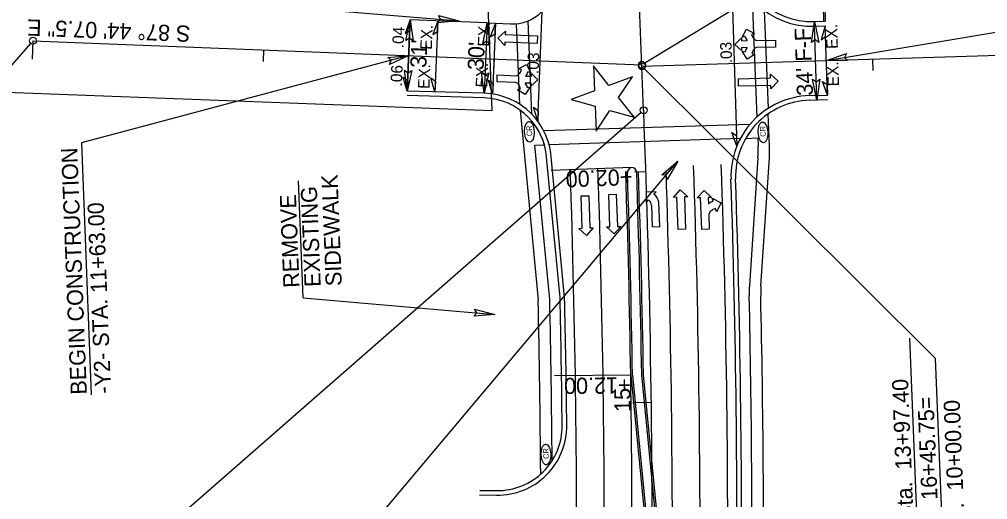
# Model space of a CAD drawing. Extents: x 1627861 to 1629601, y 761281 to 766239.
# Drawn here: x 1628215.6 to 1628635.3, y 761933.4 to 762141.5 of the extents above; entities that cross this region are included whole.
import ezdxf

# ---------------------------------------------------------------- set-up
doc = ezdxf.new("R2010")
doc.units = 0
for name, color, linetype in [('Cogo Default Point CELL', 7, 'Continuous'), ('Default', 7, 'Continuous'), ('Exist Other Culture Sign Leader', 7, 'Continuous'), ('Exist Property Tie Line Leader', 7, 'Continuous'), ('Exist Property Tie Line Text', 7, 'Continuous'), ('Exist Right of Way Line Leader', 7, 'Continuous'), ('Exist Right of Way Monument Leader', 7, 'Continuous'), ('Exist Right of Way Monument Text', 7, 'Continuous'), ('Exist Utilities Gas Meter CELL', 7, 'Continuous'), ('Exist Utilities Gas Meter Cogo Elevation', 7, 'Continuous'), ('Exist Utilities Gas Meter Cogo Number', 7, 'Continuous'), ('Exist Utilities Gas UG Line', 7, 'Continuous'), ('Exist Utilities Other Unknown UG SUE Text', 7, 'Continuous'), ('Exist Utilities Power UG Cable SUE LOS B Cogo Elevation', 7, 'Continuous'), ('Exist Utilities Power UG Cable SUE LOS B Cogo Point CELL', 7, 'Continuous'), ('Exist Utilities Telephone UG Cable SUE LOS B Cogo Comment', 7, 'Continuous'), ('Exist Utilities Telephone UG Cable SUE LOS B Cogo Number', 7, 'Continuous'), ('Exist Utilities Water Fire Hydrant Cogo Elevation', 7, 'Continuous'), ('Exist Utilities Water Fire Hydrant Cogo Number', 7, 'Continuous'), ('Exist Utilities Water Meter Cogo Elevation', 7, 'Continuous'), ('Exist Utilities Water UG Line SUE LOS B Cogo Number', 7, 'Continuous'), ('Exist Utilities Water Valve CELL', 7, 'Continuous'), ('Scratch_Level_0', 7, 'Continuous'), ('Typical Terminator CELL', 7, 'Continuous')]:
    doc.layers.add(name, color=color, linetype=linetype)

msp = doc.modelspace()

# ---------------------------------------------------------------- linework, layer by layer
at = {"layer": 'Default'}
msp.add_line((1628484.93, 762039.42), (1628484.96, 762039.39), dxfattribs=at)
at = {"layer": 'Exist Other Culture Sign Leader'}
msp.add_line((1628565.43, 762123.69), (1628664.46, 762140.15), dxfattribs=at)
at = {"layer": 'Exist Property Tie Line Text'}
for p, q in [((1628321.43, 762128.28), (1628321.23, 762123.29)), ((1628421.35, 762124.33), (1628421.15, 762119.34)), ((1628585.42, 762124.31), (1628585.58, 762119.32)), ((1628487.2, 762075.46), (1628482.2, 762075.29))]:
    msp.add_line(p, q, dxfattribs=at)
at = {"layer": 'Exist Right of Way Line Leader'}
for p, q in [((1628486.68, 762122.66), (1628711.64, 762259.34)), ((1628220.51, 762131.12), (1628175.92, 762080.71)), ((1628486.53, 762120.12), (1628612.77, 761994.56)), ((1628485.09, 762101.12), (1628288.18, 761928.9)), ((1628606.22, 761887.58), (1628601.66, 762003.32)), ((1628617.3, 761879.65), (1628612.77, 761994.56))]:
    msp.add_line(p, q, dxfattribs=at)
for centre in [(1628221.51, 762132.23), (1628485.45, 762121.8), (1628485.47, 762121.18), (1628485.47, 762121.18), (1628486.22, 762102.11)]:
    msp.add_circle(centre, 1.5, dxfattribs=at)
at = {"layer": 'Exist Right of Way Monument Leader'}
for p, q in [((1628423.01, 762133.37), (1628426.3, 762136.43)), ((1628426.3, 762136.43), (1628426.23, 762134.94)), ((1628528.86, 762133.77), (1628530.79, 762137.31)), ((1628530.79, 762137.31), (1628534.24, 762135.38)), ((1628426.03, 762130.14), (1628423.01, 762133.37)), ((1628426.09, 762131.64), (1628426.03, 762130.14)), ((1628440.08, 762131.04), (1628426.09, 762131.64)), ((1628426.23, 762134.94), (1628440.22, 762134.34)), ((1628440.22, 762134.34), (1628440.08, 762131.04)), ((1628525.75, 762130.63), (1628528.57, 762133.52)), ((1628528.57, 762133.52), (1628528.6, 762132.25)), ((1628528.6, 762132.25), (1628531.13, 762132.3)), ((1628530.12, 762134.18), (1628528.86, 762133.77)), ((1628534.24, 762135.38), (1628532.98, 762134.97)), ((1628535.13, 762132.37), (1628543.37, 762132.53)), ((1628543.37, 762132.53), (1628543.42, 762129.51)), ((1628528.68, 762127.96), (1628525.75, 762130.63)), ((1628531.14, 762129.27), (1628528.65, 762129.23)), ((1628528.65, 762129.23), (1628528.68, 762127.96)), ((1628531.04, 762124.3), (1628528.98, 762127.72)), ((1628528.98, 762127.72), (1628530.25, 762127.36)), ((1628543.42, 762129.51), (1628535.14, 762129.35)), ((1628534.41, 762126.31), (1628531.04, 762124.3)), ((1628533.14, 762126.68), (1628534.41, 762126.31)), ((1628431.97, 762120.07), (1628435.46, 762121.88)), ((1628433.22, 762119.63), (1628431.97, 762120.07)), ((1628435.46, 762121.88), (1628437.31, 762118.33)), ((1628422.65, 762114.42), (1628422.78, 762117.44)), ((1628422.78, 762117.44), (1628431.06, 762117.08)), ((1628435.05, 762116.92), (1628437.54, 762116.81)), ((1628437.31, 762118.33), (1628436.06, 762118.78)), ((1628440.35, 762115.23), (1628437.36, 762112.52)), ((1628437.54, 762116.81), (1628437.59, 762118.08)), ((1628437.59, 762118.08), (1628440.35, 762115.23)), ((1628527.27, 762115.79), (1628541.27, 762116.19)), ((1628527.37, 762112.49), (1628527.27, 762115.79)), ((1628541.27, 762116.19), (1628541.22, 762117.69)), ((1628541.22, 762117.69), (1628544.46, 762114.68)), ((1628430.88, 762114.07), (1628422.65, 762114.42)), ((1628431.58, 762111.01), (1628432.87, 762111.35)), ((1628434.91, 762108.87), (1628431.58, 762111.01)), ((1628437.41, 762113.79), (1628434.88, 762113.9)), ((1628437.05, 762112.29), (1628434.91, 762108.87)), ((1628435.77, 762111.96), (1628437.05, 762112.29)), ((1628437.36, 762112.52), (1628437.41, 762113.79)), ((1628541.36, 762112.89), (1628527.37, 762112.49)), ((1628541.4, 762111.39), (1628541.36, 762112.89)), ((1628544.46, 762114.68), (1628541.4, 762111.39)), ((1628459.1, 762064.96), (1628462.39, 762065.08)), ((1628459.6, 762050.97), (1628459.1, 762064.96)), ((1628462.39, 762065.08), (1628462.9, 762051.09)), ((1628471.07, 762065.62), (1628474.37, 762065.74)), ((1628471.57, 762051.63), (1628471.07, 762065.62)), ((1628474.37, 762065.74), (1628474.87, 762051.75)), ((1628491.63, 762066.77), (1628487.24, 762066.66)), ((1628487.24, 762066.66), (1628487.35, 762062.16)), ((1628490.62, 762065.68), (1628491.63, 762066.77)), ((1628499.12, 762064.37), (1628502.11, 762067.63)), ((1628502.11, 762067.63), (1628505.42, 762064.6)), ((1628505.42, 762064.6), (1628503.92, 762064.54)), ((1628503.92, 762064.54), (1628504.42, 762050.55)), ((1628509.38, 762064.15), (1628512.42, 762067.36)), ((1628512.42, 762067.36), (1628515.68, 762064.37)), ((1628487.35, 762062.16), (1628488.36, 762063.25)), ((1628489.6, 762060.79), (1628489.93, 762051.65)), ((1628493.22, 762051.77), (1628492.85, 762062.31)), ((1628500.62, 762064.43), (1628499.12, 762064.37)), ((1628501.12, 762050.44), (1628500.62, 762064.43)), ((1628510.88, 762064.2), (1628509.38, 762064.15)), ((1628511.38, 762050.41), (1628510.88, 762064.2)), ((1628515.68, 762064.37), (1628514.18, 762064.32)), ((1628514.18, 762064.32), (1628514.28, 762061.47)), ((1628516.34, 762062.65), (1628515.89, 762064.08)), ((1628515.89, 762064.08), (1628519.82, 762062.02)), ((1628519.82, 762062.02), (1628517.76, 762058.09)), ((1628514.44, 762056.98), (1628514.67, 762050.53)), ((1628517.76, 762058.09), (1628517.31, 762059.48)), ((1628458.1, 762050.91), (1628459.6, 762050.97)), ((1628461.41, 762047.88), (1628458.1, 762050.91)), ((1628464.4, 762051.14), (1628461.41, 762047.88)), ((1628462.9, 762051.09), (1628464.4, 762051.14)), ((1628470.08, 762051.57), (1628471.57, 762051.63)), ((1628473.39, 762048.54), (1628470.08, 762051.57)), ((1628476.37, 762051.8), (1628473.39, 762048.54)), ((1628474.87, 762051.75), (1628476.37, 762051.8)), ((1628489.93, 762051.65), (1628493.22, 762051.77)), ((1628504.42, 762050.55), (1628501.12, 762050.44)), ((1628514.67, 762050.53), (1628511.38, 762050.41))]:
    msp.add_line(p, q, dxfattribs=at)
for centre, radius, start, end in [((1628534.02, 762135.03), 4, 192.3559, 223.2455), ((1628536.88, 762135.86), 4, 192.725, 223.6552), ((1628535.73, 762134.57), 2.28, 220.1651, 254.9311), ((1628534.18, 762126.67), 4, 139.3352, 170.1117), ((1628537.07, 762125.95), 4, 138.5287, 169.7414), ((1628535.87, 762127.2), 2.28, 109.0209, 142.0188), ((1628429.34, 762120.59), 4, 315.0139, 346.2266), ((1628430.46, 762119.28), 2.28, 285.5061, 318.504), ((1628432.18, 762119.7), 4, 315.8204, 346.5968), ((1628430.15, 762111.91), 2.28, 36.6503, 71.4163), ((1628428.92, 762110.69), 4, 9.2102, 40.1404), ((1628431.82, 762111.34), 4, 8.841, 39.7307), ((1628487.7, 762061.33), 5.25, 10.7347, 56.0464), ((1628486.34, 762060.69), 3.28, 2.0586, 51.7168), ((1628517.39, 762058.33), 4.43, 103.6494, 134.528), ((1628516.91, 762056.42), 2.52, 131.1317, 167.4437), ((1628518.36, 762055.17), 4.43, 103.7683, 134.6218)]:
    msp.add_arc(centre, radius, start, end, dxfattribs=at)
at = {"layer": 'Exist Right of Way Monument Text'}
for p, q in [((1628418.35, 762139.93), (1628384.99, 762141.3)), ((1628418.35, 762139.92), (1628428.54, 762139.52)), ((1628560.31, 762138.53), (1628564.96, 762138.68)), ((1628417.14, 762109.45), (1628383.77, 762110.42)), ((1628557.96, 762108.45), (1628565.9, 762108.7)), ((1628451.97, 762021.15), (1628446.25, 762080.52)), ((1628415.12, 761935.4), (1628422.5, 761935.31))]:
    msp.add_line(p, q, dxfattribs=at)
for centre, radius, start, end in [((1628559.22, 762173.52), 35, 182.2582, 271.7963), ((1628429.25, 762157.5), 18, 267.7354, 2.2582), ((1628416.27, 762079.46), 30, 2.0159, 88.3359), ((1628559.06, 762073.46), 35, 91.7963, 181.8855), ((1623719.93, 761914.16), 4806.75, 359.5044, 1.88553), ((1623719.93, 761914.16), 4733.25, 0.62309, 1.29528), ((1628422.9, 761965.3), 30, 269.2458, 0.6231)]:
    msp.add_arc(centre, radius, start, end, dxfattribs=at)
at = {"layer": 'Exist Utilities Gas Meter CELL'}
for p, q in [((1628486.22, 762102.11), (1628373.12, 764970.45)), ((1628221.51, 762132.23), (1628485.45, 762121.8)), ((1628221.51, 762132.23), (1628485.45, 762121.8)), ((1628485.47, 762121.18), (1628785.32, 762130.58))]:
    msp.add_line(p, q, dxfattribs=at)
msp.add_arc((1623719.93, 761914.16), 4770, 359.5044, 2.25819, dxfattribs=at)
at = {"layer": 'Exist Utilities Gas Meter Cogo Elevation'}
for p, q in [((1628560.25, 762140.53), (1628564.9, 762140.68)), ((1628417.08, 762107.46), (1628383.71, 762108.53)), ((1628558.02, 762106.45), (1628565.96, 762106.7)), ((1628449.98, 762020.96), (1628444.26, 762080.33)), ((1628415.14, 761937.4), (1628421.53, 761937.32)), ((1628415.14, 761937.4), (1628422.53, 761937.31))]:
    msp.add_line(p, q, dxfattribs=at)
for centre, radius, start, end in [((1628559.22, 762173.52), 33, 182.2582, 271.7963), ((1628416.27, 762079.46), 28, 2.0159, 88.3359), ((1628559.06, 762073.46), 33, 91.7963, 181.8855), ((1623719.93, 761914.16), 4808.75, 359.5044, 1.88551), ((1623719.93, 761914.16), 4731.25, 0.62309, 1.29528), ((1628422.9, 761965.3), 28, 269.2458, 0.6231)]:
    msp.add_arc(centre, radius, start, end, dxfattribs=at)
at = {"layer": 'Exist Utilities Gas Meter Cogo Number'}
for points in [[(1628383.09, 762132.37), (1628384.99, 762141.3), (1628386.24, 762132.2), (1628384.68, 762133.41)], [(1628397.22, 762143.18), (1628406.06, 762140.89), (1628396.91, 762140.04), (1628398.19, 762141.54)], [(1628558.98, 762131.49), (1628560.25, 762140.53), (1628562.13, 762131.54), (1628560.5, 762132.64)], [(1628416.44, 762130.96), (1628418.34, 762139.89), (1628419.59, 762130.78), (1628418.03, 762132)], [(1628375.29, 762124.97), (1628384.38, 762125.79), (1628376.05, 762121.92), (1628376.75, 762123.76)], [(1628574.56, 762123.63), (1628565.43, 762123.69), (1628574.1, 762126.75), (1628573.22, 762124.98)], [(1628385.68, 762119.35), (1628383.77, 762110.42), (1628382.53, 762119.53), (1628384.09, 762118.31)], [(1628419.04, 762118.38), (1628417.14, 762109.45), (1628415.9, 762118.56), (1628417.45, 762117.35)], [(1628562.58, 762115.59), (1628561.32, 762106.55), (1628559.43, 762115.55), (1628561.07, 762114.45)], [(1628494.06, 762074.17), (1628501.04, 762080.06), (1628496.44, 762072.1), (1628495.95, 762074.01)], [(1628412.95, 762015.96), (1628421.78, 762013.63), (1628412.63, 762012.82), (1628413.91, 762014.32)]]:
    msp.add_lwpolyline(points, close=True, dxfattribs=at)
at = {"layer": 'Exist Utilities Gas UG Line'}
for p, q in [((1628480.61, 761987.35), (1628492.92, 761862.47)), ((1628498.42, 761862.44), (1628486.11, 761987.44))]:
    msp.add_line(p, q, dxfattribs=at)
for radius, start, end in [(4790.75, 359.5044, 1.96193), (4802.75, 359.5044, 1.96193), (4737.25, 359.5044, 1.96193), (4749.25, 359.5044, 1.96193), (4761.25, 0.88088, 1.93787), (4766.75, 0.88088, 1.94119), (4778.75, 359.5044, 1.93871), (4761.25, 359.5044, 0.88088)]:
    msp.add_arc((1623719.93, 761914.16), radius, start, end, dxfattribs=at)
at = {"layer": 'Exist Utilities Other Unknown UG SUE Text'}
for p, q in [((1628481.36, 761987.37), (1628493.67, 761862.47)), ((1628497.67, 761862.44), (1628485.36, 761987.43))]:
    msp.add_line(p, q, dxfattribs=at)
for centre, radius, start, end in [((1628481.2, 762075.26), 2, 1.9379, 181.9379), ((1623719.93, 761914.16), 4762, 0.88088, 1.93788), ((1623719.93, 761914.16), 4766, 0.88088, 1.93788)]:
    msp.add_arc(centre, radius, start, end, dxfattribs=at)
at = {"layer": 'Exist Utilities Power UG Cable SUE LOS B Cogo Elevation'}
msp.add_lwpolyline([(1628465.18, 762103.83), (1628465.61, 762093.02), (1628471.61, 762102.01), (1628482.04, 762099.08), (1628475.33, 762107.59), (1628481.34, 762116.59), (1628471.19, 762112.84), (1628464.48, 762121.34), (1628464.91, 762110.52), (1628454.75, 762106.76), (1628465.18, 762103.83)], dxfattribs=at)
at = {"layer": 'Exist Utilities Power UG Cable SUE LOS B Cogo Point CELL'}
msp.add_line((1628561.32, 762106.55), (1628560.31, 762138.53), dxfattribs=at)
at = {"layer": 'Exist Utilities Telephone UG Cable SUE LOS B Cogo Comment'}
for p, q in [((1628533.3, 762150), (1628535.3, 762099.17)), ((1628538.49, 762145.32), (1628540.16, 762102.92)), ((1628437.7, 762100.45), (1628436.11, 762140.86)), ((1628432.53, 762104.67), (1628431.16, 762139.6)), ((1628532.26, 762095.98), (1628442.98, 762093.12)), ((1628528.13, 762089.85), (1628445.26, 762087.19))]:
    msp.add_line(p, q, dxfattribs=at)
at = {"layer": 'Exist Utilities Telephone UG Cable SUE LOS B Cogo Number'}
for p, q in [((1628564.03, 762147.19), (1628564.23, 762140.66)), ((1628564.69, 762147.22), (1628564.9, 762140.68))]:
    msp.add_line(p, q, dxfattribs=at)
at = {"layer": 'Exist Utilities Water Fire Hydrant Cogo Elevation'}
for centre in [(1628436.67, 762092.76), (1628537.95, 762092.52), (1628443.87, 761952.93)]:
    msp.add_ellipse(centre, major_axis=(-0.18, 4.48), ratio=0.462467, dxfattribs=at)
at = {"layer": 'Exist Utilities Water Fire Hydrant Cogo Number'}
for p, q in [((1628420.61, 762102.01), (1628396.89, 762704.96)), ((1628075.65, 762115.08), (1628420.61, 762102.01))]:
    msp.add_line(p, q, dxfattribs=at)
at = {"layer": 'Exist Utilities Water Meter Cogo Elevation'}
for p, q in [((1628221.51, 762132.23), (1628221.19, 762124.24)), ((1628489.53, 761975.49), (1628481.53, 761975.39))]:
    msp.add_line(p, q, dxfattribs=at)
at = {"layer": 'Exist Utilities Water UG Line SUE LOS B Cogo Number'}
for p, q in [((1628524.3, 762159.05), (1628526.58, 762086.51)), ((1628440.3, 762097.42), (1628442.18, 762144.99)), ((1628383.77, 762110.42), (1628384.99, 762141.3)), ((1628396.98, 762140.81), (1628395.77, 762110.07)), ((1628421.96, 762139.82), (1628420.75, 762109.08)), ((1628565.9, 762108.7), (1628564.96, 762138.68))]:
    msp.add_line(p, q, dxfattribs=at)
at = {"layer": 'Exist Utilities Water Valve CELL'}
for p, q in [((1628432.63, 762102.19), (1628440.5, 762019.75)), ((1628540.8, 762086.74), (1628540.25, 762100.58)), ((1628530.46, 762089.94), (1628535.66, 762090.14)), ((1628535.66, 762090.14), (1628535.79, 762086.81)), ((1628439.11, 762086.94), (1628443.21, 762087.11)), ((1628445.49, 762020.04), (1628439.11, 762086.94)), ((1628535.72, 762081.55), (1628532.07, 762026.18)), ((1628537.07, 762026.07), (1628540.73, 762081.49))]:
    msp.add_line(p, q, dxfattribs=at)
for centre, radius, start, end in [((1628416.27, 762079.46), 28, 15.8373, 54.2427), ((1628559.06, 762073.46), 33, 124.7428, 150.0507), ((1628485.83, 762084.84), 50, 356.2292, 2.2582), ((1628490.83, 762084.77), 50, 356.2292, 2.2582), ((1628581.96, 762022.89), 50, 176.2292, 181.2812), ((1628586.97, 762022.79), 50, 176.2292, 181.2786), ((1623719.93, 761914.16), 4721.75, 0.36779, 1.28142), ((1623719.93, 761914.16), 4726.75, 0.43835, 1.28362), ((1623719.93, 761914.16), 4813.25, 359.5044, 1.28119), ((1623719.93, 761914.16), 4818.25, 359.5044, 1.2786)]:
    msp.add_arc(centre, radius, start, end, dxfattribs=at)
at = {"layer": 'Scratch_Level_0'}
for p, q in [((1628240.75, 762154.52), (1628406.06, 762140.89)), ((1628384.99, 762141.3), (1628383.77, 762110.42)), ((1628418.34, 762139.89), (1628417.14, 762109.45)), ((1628384.38, 762125.79), (1628242.5, 762087.98)), ((1628242.5, 762087.98), (1628246.8, 761978.81)), ((1628349.57, 761900.08), (1628501.04, 762080.06)), ((1628481.13, 762077.25), (1628446.16, 762076.06)), ((1628338.59, 762020.87), (1628336.59, 762071.58)), ((1628338.59, 762020.87), (1628421.78, 762013.63)), ((1628480.61, 761987.35), (1628447.62, 761987.05))]:
    msp.add_line(p, q, dxfattribs=at)
at = {"layer": 'Typical Terminator CELL'}
for points in [[(1628384.99, 762141.3), (1628382.78, 762135.38), (1628384.83, 762136.68)], [(1628396.98, 762140.81), (1628394.77, 762134.88), (1628396.82, 762136.18)], [(1628421.96, 762139.82), (1628419.75, 762133.89), (1628421.8, 762135.2)], [(1628564.96, 762138.68), (1628563.15, 762132.62), (1628565.11, 762134.06)], [(1628383.77, 762110.42), (1628382.01, 762116.5), (1628383.96, 762115.04)], [(1628395.77, 762110.07), (1628394.01, 762116.15), (1628395.95, 762114.69)], [(1628420.75, 762109.08), (1628418.99, 762115.16), (1628420.93, 762113.71)], [(1628565.9, 762108.7), (1628563.72, 762114.63), (1628565.76, 762113.32)], [(1628440.3, 762097.42), (1628438.54, 762103.49), (1628440.49, 762102.04)], [(1628526.58, 762086.51), (1628524.39, 762092.44), (1628526.43, 762091.13)]]:
    msp.add_lwpolyline(points, close=True, dxfattribs=at)

# ---------------------------------------------------------------- texts
at = {"layer": 'Cogo Default Point CELL'}
msp.add_text('S 87%%d 44\' 07.5" E', height=7, rotation=177.7354, dxfattribs=at).set_placement((1628289.89, 762138.7))
at = {"layer": 'Exist Other Culture Sign Leader'}
for s, p in [('BEGIN CONSTRUCTION', (1628244.89, 761979)), ('-Y2- STA. 11+63.00', (1628255.38, 761979.42))]:
    msp.add_text(s, height=7, rotation=92.2582, dxfattribs=at).set_placement(p)
at = {"layer": 'Exist Property Tie Line Leader'}
msp.add_text('15', height=7, rotation=90.7367, dxfattribs=at).set_placement((1628480.58, 761971.43))
at = {"layer": 'Exist Right of Way Line Leader'}
for s, p in [('-L- PRC Sta.  13+97.40', (1628604.67, 761888.35)), ('-L- POT Sta. 16+45.75=', (1628615.8, 761878.29)), ('-Y- POT Sta.  10+00.00', (1628627.06, 761878.74))]:
    msp.add_text(s, height=7, rotation=92.2582, dxfattribs=at).set_placement(p)
at = {"layer": 'Exist Utilities Power UG Cable SUE LOS B Cogo Point CELL'}
for s, rotation, p in [("34' F-F", 92.0586, (1628559.65, 762108.54)), ("31'", 87.6733, (1628392, 762120.34)), ("30'", 87.6733, (1628416.86, 762119.38)), ('SIDEWALK', 92.2582, (1628355.42, 762026.04)), ('REMOVE ', 92.2582, (1628337.08, 762025.32)), ('EXISTING', 92.2582, (1628346.25, 762025.68))]:
    msp.add_text(s, height=7, rotation=rotation, dxfattribs=at).set_placement(p)
at = {"layer": 'Exist Utilities Water Fire Hydrant Cogo Elevation'}
for p in [(1628437.92, 762090.92), (1628539.2, 762090.69), (1628445.13, 761951.09)]:
    msp.add_text('CR', height=2.4, rotation=92.2582, dxfattribs=at).set_placement(p)
at = {"layer": 'Exist Utilities Water UG Line SUE LOS B Cogo Number'}
for s, rotation, p in [('.04', 87.7354, (1628382.19, 762128.91)), ('EX.', 87.7354, (1628394.37, 762128.26)), ('EX.', 87.7354, (1628419.28, 762129.57)), ('EX.', 91.7963, (1628570.42, 762128.78)), ('.03', 91.7963, (1628524.6, 762122.52)), ('.03', 87.7354, (1628440.63, 762117.76)), ('.06', 87.7354, (1628381.43, 762112.34)), ('EX.', 87.7354, (1628393.35, 762111.27)), ('EX.', 87.7354, (1628418.37, 762111.86)), ('EX.', 91.7963, (1628570.93, 762112.56))]:
    msp.add_text(s, height=5, rotation=rotation, dxfattribs=at).set_placement(p)
at = {"layer": 'Scratch_Level_0'}
for s, rotation, p in [('+02.00', 181.9619, (1628481.17, 762076.7)), ('+12.00', 180.5205, (1628480.56, 761986.42))]:
    msp.add_text(s, height=7, rotation=rotation, dxfattribs=at).set_placement(p)

doc.saveas('drawing.dxf')
